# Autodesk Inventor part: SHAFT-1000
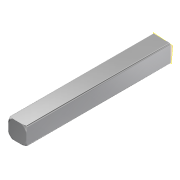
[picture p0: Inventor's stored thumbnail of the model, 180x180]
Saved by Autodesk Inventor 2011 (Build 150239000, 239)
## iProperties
Created: 2007-08
Part Number: SHAFT-1000
Material: Stainless Steel
Document SubType Name: Modeling
Density: 8.08 g/cm^3
Mass: 2.05689 g
Surface Area: 3.30995 cm^2
Volume: 0.254566 cm^3
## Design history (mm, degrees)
feature "Base1"
workaxis "Work Axis1"
  workplane "Work Plane1"
  workplane "Work Plane2"
workplane "Work Plane3"
split "Split1"
body "Solid1"
